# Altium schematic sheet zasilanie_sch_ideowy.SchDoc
size A4; SheetNumber: 2; SheetTotal: 2
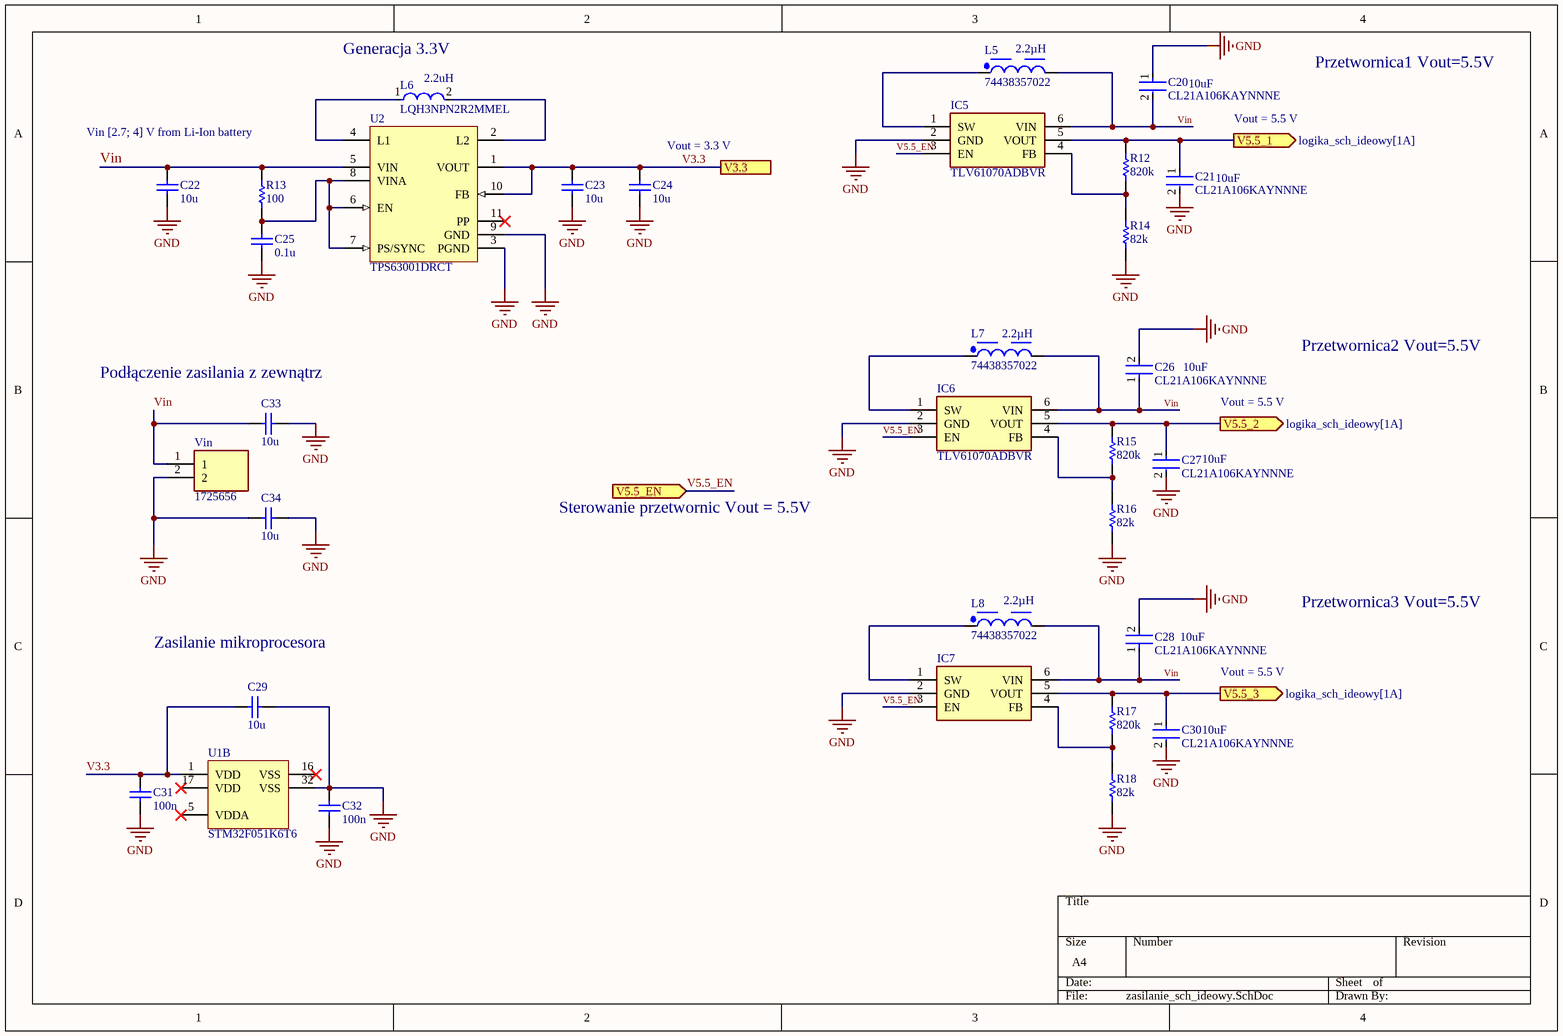
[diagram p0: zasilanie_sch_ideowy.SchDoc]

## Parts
C20  CL21A106KAYNNNE  Capacitance: 10uF  [FP-CL21-IPC_A]
C21  CL21A106KAYNNNE  Capacitance: 10uF  [FP-CL21-IPC_A]
C22  value 10u  [Capacitor_1206]  (hidden comment: Capacitor)
C23  value 10u  [Capacitor_1206]  (hidden comment: Capacitor)
C24  value 10u  [Capacitor_0805]  (hidden comment: Capacitor)
C25  value 0.1u  [Capacitor_1206]  (hidden comment: Capacitor)
C26  CL21A106KAYNNNE  Capacitance: 10uF  [FP-CL21-IPC_A]
C27  CL21A106KAYNNNE  Capacitance: 10uF  [FP-CL21-IPC_A]
C28  CL21A106KAYNNNE  Capacitance: 10uF  [FP-CL21-IPC_A]
C29  value 10u  [Capacitor_1206]  (hidden comment: Capacitor)
C30  CL21A106KAYNNNE  Capacitance: 10uF  [FP-CL21-IPC_A]
C31  value 100n  [Capacitor_0805]  (hidden comment: Capacitor)
C32  value 100n  [Capacitor_0805]  (hidden comment: Capacitor)
C33  value 10u  [Capacitor_1206]  (hidden comment: Capacitor)
C34  value 10u  [Capacitor_1206]  (hidden comment: Capacitor)
IC5  TLV61070ADBVR  [SOT95P280X145-6N]
IC6  TLV61070ADBVR  [SOT95P280X145-6N]
IC7  (no value)  [SOT95P280X145-6N]
L5  74438357022  Inductance: 2.2µH  [WE-MAPI_4030]
L6  LQH3NPN2R2MMEL  Inductance: 2.2uH  [FP-LQH3NPH_ME-MFG]
L7  74438357022  Inductance: 2.2µH  [WE-MAPI_4030]
L8  74438357022  Inductance: 2.2µH  [WE-MAPI_4030]
R12  value 820k  [Resistor_0805]  (hidden comment: Resistor)
R13  value 100  [Resistor_0805]  (hidden comment: Resistor)
R14  value 82k  [Resistor_0805]  (hidden comment: Resistor)
R15  value 820k  [Resistor_0805]  (hidden comment: Resistor)
R16  value 82k  [Resistor_0805]  (hidden comment: Resistor)
R17  value 820k  [Resistor_0805]  (hidden comment: Resistor)
R18  value 82k  [Resistor_0805]  (hidden comment: Resistor)
U1  STM32F051K6T6  [STM-LQFP32_L]  (part B of 2)
U2  TPS63001DRCT  [DRC0010J_V]
Vin  1725656  [1725656]

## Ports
V3.3 (see logika_sch_ideowy[1A]), V5.5_1 (out, see logika_sch_ideowy[1A]), V5.5_2 (out, see logika_sch_ideowy[1A]), V5.5_3 (out, see logika_sch_ideowy[1A]), V5.5_EN (in, see logika_sch_ideowy[1A])

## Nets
GND: C20.1 C21.2 C22.1 C23.1 C24.1 C25.1 C26.2 C27.2 C28.2 C29.2 C30.2 C31.1 C32.1 C32.2 C33.1 C34.1 C34.2 IC5.2(GND) IC6.2(GND) IC7.2(GND) R14.1 R16.1 R18.1 U1.32(VSS) U2.3(PGND) U2.9(GND) Vin.2
V3.3: C23.2 C24.2 C29.1 C31.2 U1.1(VDD) U2.1(VOUT) U2.10(FB) ; port V3.3
V5.5_1: C21.1 IC5.5(VOUT) R12.2 ; port V5.5_1
V5.5_2: C27.1 IC6.5(VOUT) R15.2 ; port V5.5_2
V5.5_3: C30.1 IC7.5(VOUT) R17.2 ; port V5.5_3
V5.5_EN: IC5.3(EN) IC6.3(EN) IC7.3(EN) ; port V5.5_EN
Vin: C20.2 C22.2 C26.1 C28.1 C33.2 IC5.6(VIN) IC6.6(VIN) IC7.6(VIN) L5.2 L7.2 L8.2 R13.2 U2.5(VIN) Vin.1
NetC25_2: C25.2 R13.1 U2.6(EN) U2.7(PS/SYNC) U2.8(VINA)
NetIC5_1: IC5.1(SW) L5.1
NetIC5_4: IC5.4(FB) R12.1 R14.2
NetIC6_1: IC6.1(SW) L7.1
NetIC6_4: IC6.4(FB) R15.1 R16.2
NetIC7_1: IC7.1(SW) L8.1
NetIC7_4: IC7.4(FB) R17.1 R18.2
NetL6_1: L6.1 U2.4(L1)
NetL6_2: L6.2 U2.2(L2)

Not connected (* = marked no-connect by the designer): U1 5(VDDA)* 16(VSS)* 17(VDD)*; U2 11(PP)*

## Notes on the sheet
- (near L6) Generacja 3.3V
- Przetwornica1 Vout=5.5V
- Vin [2.7; 4] V from Li-Ion battery
- (near C24) Vout = 3.3 V
- Vout = 5.5 V
- (near C33) Podłączenie zasilania z zewnątrz
- Przetwornica2 Vout=5.5V
- Sterowanie przetwornic Vout = 5.5V
- Zasilanie mikroprocesora
- Przetwornica3 Vout=5.5V

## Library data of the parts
C20 C21 C26-C28 C30 = CMP-13271-002975-1: CL21 Series 0805 10uF 25V ±10% Tolerance X5R Multilayer Ceramic Chip Capacitor
C22-C25 C29 C31-C34 = Capacitor: SimulationGenericComponent: True
IC5-IC7 = TLV61070ADBVR: Integrated Circuit; Manufacturer_Name: Texas Instruments
L5 L7 L8 = CMP-03913-81252529-2: 74438357022 Fixed Ind 2.2UH 5.2A 26 Mohm SMD; Inductance Tolerance: 20%; Test Frequency: 100kHz; DC Resistance (DCR): 22mΩ; Series Resistance: 26mΩ; Saturation Current: 7A; Self Resonant Frequency: 35MHz
L6 = CMP-06042-009066-1: Wire Wound Ferrite Inductor for Power Lines 2.2μH ±20% 0.078Ω 2100mA 1212; Shielding: Shielded; DC Resistance (DCR): 78mR; Saturation Current: 1.8A; Test Frequency: 1MHz; Current Rating: 2.1A; Self Resonant Frequency: 60MHz
R12-R18 = Resistor: TC1: 0; SimulationGenericComponent: True
U1 = CMP-0304-00023-2: ARM Cortex-M0 32-bit MCU, 32 KB Flash, 4 KB Internal RAM, 25 I/Os, 32-pin LQFP, -40 to 85 degC, Tray; I/Os (High Current): 25; Operating Frequency(F) (Processor speed) (MHz): 48; FLASH Size (Prog) (kB): 32; Internal RAM Size (kB): 4; Supply Voltage(Vcc) min (V): 2
U2 = CMP-0345-00002-2: Buck-Boost Voltage Converter with 1.8 to 5.5 V Input and 3.3 V Output, -40 to 85 degC, 10-Pin SON (DRC), Green (RoHS & no Sb/Br); Manufacturer: Texas Instruments; Iout(Max)(A): 1.2; Dynamic Voltage Scaling: TRUE; SubFamily: Buck-Boost Regulator; Preset Vout(V): 3.3; Switching Frequency(Max)(kHz): 1500; Iq(Typ)(mA): 0.03; Regulated Outputs(#): 1; Vin(Max)(V): 5.5; Vin(Min)(V): 1.8
Vin = 1725656: 2-pin screw terminal block Connector; Manufacturer_Name: Phoenix Contact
